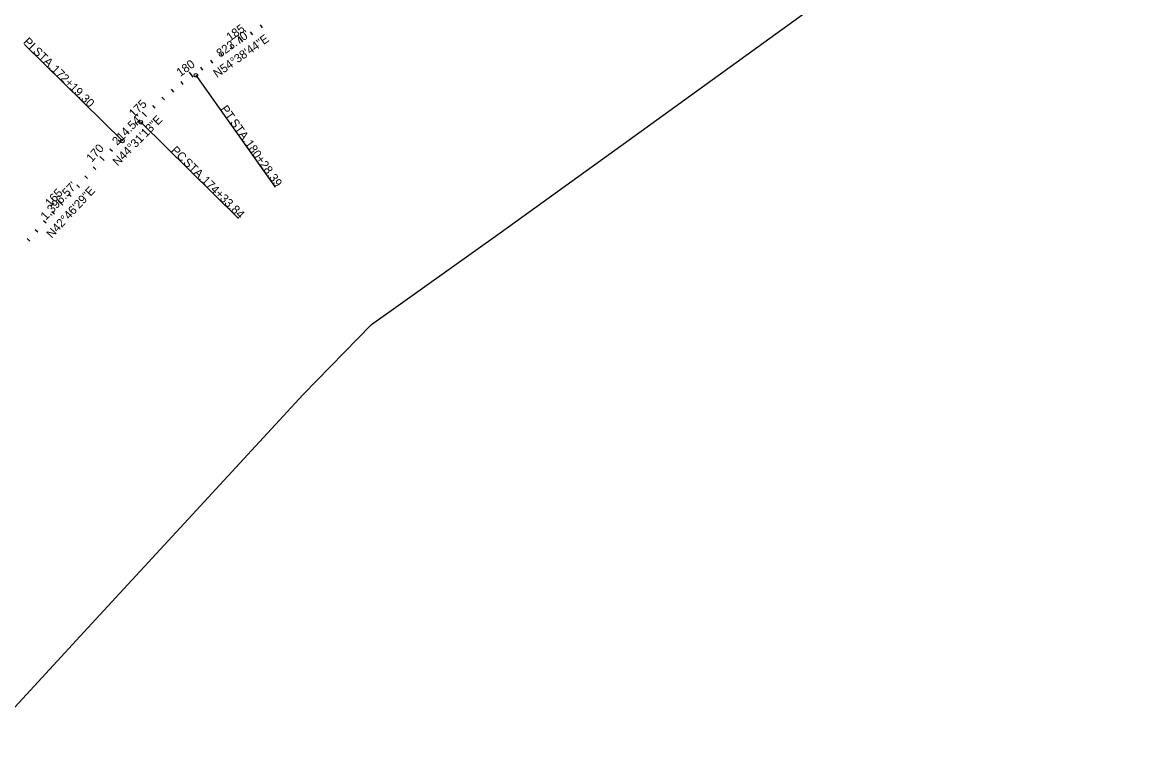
# Model space of a CAD drawing. Extents: x 187058 to 230449, y 263308 to 297406.
# Drawn here: x 199019 to 208205, y 273830 to 279748 of the extents above; entities that cross this region are included whole.
import ezdxf

# ---------------------------------------------------------------- set-up
doc = ezdxf.new("R2010")
doc.units = 0
for name, color, linetype in [('BR_X_Gen_Approach_Slab', 7, 'Continuous'), ('BR_X_SV_Deck_Top', 7, 'Continuous'), ('PV_X_Walk', 7, 'Continuous'), ('RD_X_GR_Lt', 7, 'Continuous'), ('SH_Named_Boundary', 7, 'Continuous')]:
    doc.layers.add(name, color=color, linetype=linetype)

msp = doc.modelspace()

# ---------------------------------------------------------------- linework, layer by layer
at = {"layer": 'BR_X_SV_Deck_Top'}
for p, q in [((200989.2, 279703.8), (200971.9, 279728.3)), ((200826.1, 279588.1), (200797.2, 279628.9)), ((200907.7, 279645.9), (200890.3, 279670.4)), ((200744.6, 279530.2), (200727.2, 279554.7)), ((200663, 279472.3), (200645.6, 279496.8)), ((200499.9, 279356.6), (200482.5, 279381.1)), ((200581.5, 279414.5), (200564.1, 279439)), ((200338.2, 279238.9), (200319.9, 279262.7)), ((200418.4, 279298.7), (200389.1, 279339.2)), ((200259.8, 279176.8), (200240.9, 279200)), ((200183.3, 279112.4), (200163.7, 279135.1)), ((200036.3, 278976.9), (200001.3, 279012.7)), ((200108.8, 279045.8), (200088.5, 279067.8)), ((199965.7, 278906.1), (199944.3, 278927.1)), ((199895.6, 278834.8), (199874.2, 278855.8)), ((199758, 278689.7), (199736, 278710)), ((199825.9, 278763.1), (199803.9, 278783.5)), ((199690.1, 278616.3), (199653.4, 278650.2)), ((199622.1, 278542.9), (199600.1, 278563.2)), ((199554.2, 278469.5), (199532.2, 278489.8)), ((199418.4, 278322.7), (199396.4, 278343)), ((199486.3, 278396.1), (199464.3, 278416.4)), ((199350.5, 278249.3), (199313.8, 278283.2)), ((199282.6, 278175.9), (199260.6, 278196.2)), ((199214.7, 278102.5), (199192.7, 278122.8)), ((199078.9, 277955.6), (199056.8, 277976)), ((199146.8, 278029), (199124.7, 278049.4))]:
    msp.add_line(p, q, dxfattribs=at)
at = {"layer": 'PV_X_Walk'}
for p, q in [((199839, 278777.2), (199036.9, 279566)), ((200441.5, 279315.2), (201092.4, 278397.6)), ((199989.4, 278930.2), (200791.5, 278141.4))]:
    msp.add_line(p, q, dxfattribs=at)
for centre in [(200441.5, 279315.2), (199989.4, 278930.2), (199839, 278777.2)]:
    msp.add_circle(centre, 15, dxfattribs=at)
at = {"layer": 'SH_Named_Boundary'}
msp.add_lwpolyline([(195008.2, 277231.7), (198672.7, 273830.1), (199554.8, 274786.9), (200443.3, 275747.7), (201321.4, 276698.3), (201882.1, 277272), (202936.9, 278024), (203995.3, 278787.1), (205049.1, 279548.4), (206102.9, 280309.7), (207156.7, 281070.9), (208205.3, 281824.1), (205291.9, 285887.7), (204228.8, 285124), (203175, 284362.7), (202121.2, 283601.5), (201067.4, 282840.2), (200016.9, 282082.8), (198954.7, 281325.4), (197651.3, 280093.9), (196765.1, 279134.5), (195888.3, 278186.5)], close=True, dxfattribs=at)

# ---------------------------------------------------------------- texts
at = {"layer": 'BR_X_Gen_Approach_Slab'}
for s, rotation, p in [("823.70'", 35.35441, (200640.6, 279457.7)), ("214.54'", 45.47976, (199796.4, 278735.4)), ("1,396.57'", 47.22522, (199211.6, 278122.1))]:
    msp.add_text(s, height=70, rotation=rotation, dxfattribs=at).set_placement(p)
at = {"layer": 'BR_X_SV_Deck_Top'}
for s, rotation, p in [('185', 35.35441, (200722.6, 279591.2)), ('180', 35.83787, (200314, 279300.3)), ('175', 44.353, (199933.5, 278963.9)), ('170', 47.22522, (199587.4, 278597.3)), ('165', 47.22522, (199248.5, 278231.1))]:
    msp.add_text(s, height=70, rotation=rotation, dxfattribs=at).set_placement(p)
at = {"layer": 'PV_X_Walk'}
for s, rotation, p in [('PI', 315.47976, (199021.7, 279582.5)), (' STA. ', 315.47976, (199082.1, 279523)), ('172+19.30', 315.47976, (199250.6, 279357.3)), ('PT', 305.35441, (200639.4, 279038)), (' STA. ', 305.35441, (200703.3, 278948)), ('PC', 315.47976, (200232.3, 278692.8)), ('180+28.39', 305.35441, (200840, 278755.3)), (' STA. ', 315.47976, (200314, 278612.5)), ('174+33.84', 315.47976, (200482.5, 278446.8))]:
    msp.add_text(s, height=70, rotation=rotation, dxfattribs=at).set_placement(p)
at = {"layer": 'RD_X_GR_Lt'}
for s, rotation, p in [('N54°38\'44"E', 35.35441, (200615.1, 279291.2)), ('N44°31\'13"E', 45.47976, (199800.6, 278567)), ('N42°46\'29"E', 47.22522, (199259.9, 277974.7))]:
    msp.add_text(s, height=70, rotation=rotation, dxfattribs=at).set_placement(p)

doc.saveas('drawing.dxf')
